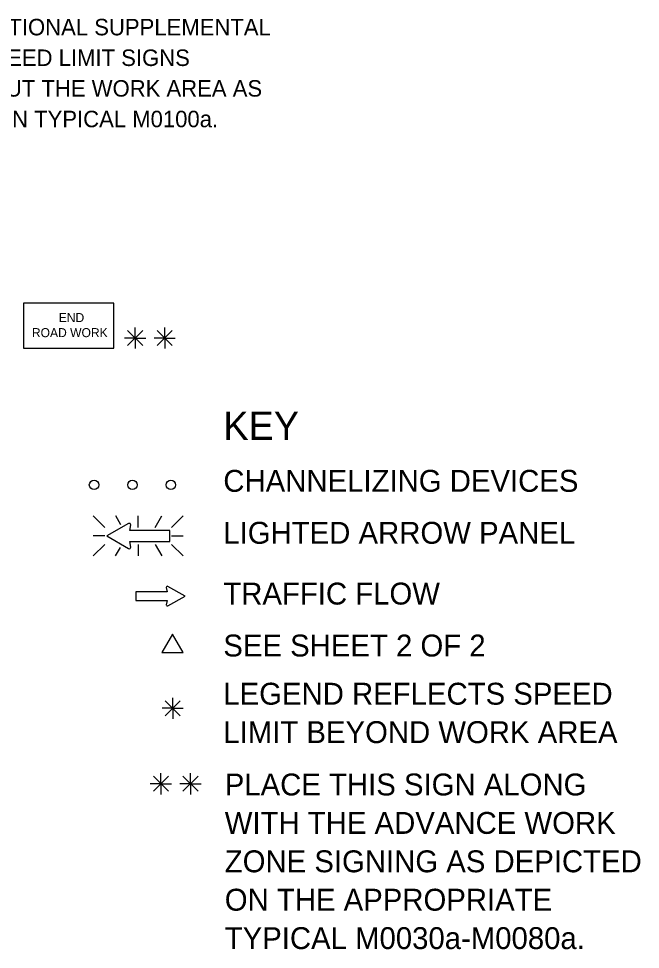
# Model space of a CAD drawing. Extents: x 16284 to 18465, y 5417 to 6974.
# Drawn here: x 17149.1 to 17412.8, y 6528.3 to 6923.3 of the extents above; entities that cross this region are included whole.
import ezdxf

# ---------------------------------------------------------------- set-up
doc = ezdxf.new("R2010")
doc.units = 0
for name, color, linetype in [('MT_SCRATCH_LEVEL_E', 7, 'Continuous'), ('TRAFFIC_SIGNS_PR', 7, 'Continuous'), ('TYPICAL_TEXT_DIMEN_EX', 7, 'Continuous'), ('TYPICAL_TEXT_DIMEN_PR', 7, 'Continuous')]:
    doc.layers.add(name, color=color, linetype=linetype)

msp = doc.modelspace()

# ---------------------------------------------------------------- linework, layer by layer
at = {"layer": 'MT_SCRATCH_LEVEL_E'}
for p, q in [((17211.71, 6681.88), (17212.03, 6680.1)), ((17219.64, 6678.25), (17212.4, 6682.36)), ((17212.03, 6680.1), (17198.77, 6680.1)), ((17198.77, 6680.1), (17198.77, 6676.36)), ((17198.77, 6676.36), (17212.03, 6676.36)), ((17212.03, 6676.36), (17211.71, 6674.58)), ((17212.4, 6674.1), (17219.64, 6678.25))]:
    msp.add_line(p, q, dxfattribs=at)
for centre, start, end in [((17212.17, 6681.95), 60.4248, 189.9638), ((17212.17, 6674.51), 170.0362, 299.7731)]:
    msp.add_arc(centre, 0.463, start, end, dxfattribs=at)
at = {"layer": 'TRAFFIC_SIGNS_PR'}
for p, q in [((17180.7, 6712.26), (17185.64, 6707.33)), ((17192.46, 6708.44), (17190.26, 6712.26)), ((17199.78, 6707.33), (17199.78, 6712.26)), ((17207.02, 6707.33), (17209.87, 6712.26)), ((17213.93, 6707.33), (17218.87, 6712.26)), ((17185.64, 6703.77), (17180.7, 6703.77)), ((17180.7, 6695.28), (17185.64, 6700.21)), ((17199.78, 6700.21), (17199.78, 6695.28)), ((17209.91, 6695.28), (17207.06, 6700.21)), ((17213.93, 6703.77), (17218.87, 6703.77)), ((17213.93, 6700.21), (17218.87, 6695.28)), ((17190.21, 6695.28), (17192.33, 6698.94))]:
    msp.add_line(p, q, dxfattribs=at)
msp.add_lwpolyline([(17151.07, 6783.41), (17189.47, 6783.41), (17189.47, 6802.61), (17151.07, 6802.61)], close=True, dxfattribs=at)
for points in [[(17195.71, 6709.05), (17186.42, 6703.77), (17195.71, 6698.45)], [(17196.59, 6699.08), (17196.19, 6701.35), (17213.2, 6701.35), (17213.2, 6706.15), (17196.19, 6706.15), (17196.59, 6708.43)]]:
    msp.add_lwpolyline(points, dxfattribs=at)
for centre in [(17181.05, 6725.46), (17197.35, 6725.46), (17213.65, 6725.46)]:
    msp.add_circle(centre, 2, dxfattribs=at)
for centre, radius, start, end in [((17196, 6708.52), 0.598, 350.7308, 118.8916), ((17196, 6698.97), 0.597, 241.4833, 9.9593)]:
    msp.add_arc(centre, radius, start, end, dxfattribs=at)
at = {"layer": 'TYPICAL_TEXT_DIMEN_PR'}
for p, q in [((17195.31, 6790.97), (17201.68, 6784.59)), ((17201.68, 6790.97), (17195.31, 6784.59)), ((17198.49, 6787.78), (17198.49, 6792.24)), ((17207.86, 6790.97), (17214.24, 6784.59)), ((17214.24, 6790.97), (17207.86, 6784.59)), ((17211.05, 6787.78), (17211.05, 6792.24)), ((17198.49, 6787.78), (17193.96, 6787.78)), ((17198.49, 6787.78), (17201.68, 6787.78)), ((17198.49, 6787.78), (17202.97, 6787.78)), ((17198.49, 6787.78), (17198.49, 6783.28)), ((17211.05, 6787.78), (17206.52, 6787.78)), ((17211.05, 6787.78), (17214.24, 6787.78)), ((17211.05, 6787.78), (17215.53, 6787.78)), ((17211.05, 6787.78), (17211.05, 6783.28)), ((17211.25, 6633.82), (17217.62, 6627.44)), ((17217.62, 6633.82), (17211.25, 6627.44)), ((17214.43, 6630.63), (17214.43, 6635.09)), ((17214.43, 6630.63), (17209.9, 6630.63)), ((17214.43, 6630.63), (17217.62, 6630.63)), ((17214.43, 6630.63), (17218.91, 6630.63)), ((17214.43, 6630.63), (17214.43, 6626.13)), ((17206.23, 6601.78), (17212.6, 6595.41)), ((17212.6, 6601.78), (17206.23, 6595.41)), ((17209.42, 6598.6), (17209.42, 6603.05)), ((17218.78, 6601.78), (17225.16, 6595.41)), ((17225.16, 6601.78), (17218.78, 6595.41)), ((17221.97, 6598.6), (17221.97, 6603.05)), ((17209.42, 6598.6), (17204.88, 6598.6)), ((17209.42, 6598.6), (17212.6, 6598.6)), ((17209.42, 6598.6), (17213.89, 6598.6)), ((17209.42, 6598.6), (17209.42, 6594.1)), ((17221.97, 6598.6), (17217.44, 6598.6)), ((17221.97, 6598.6), (17225.16, 6598.6)), ((17221.97, 6598.6), (17226.45, 6598.6)), ((17221.97, 6598.6), (17221.97, 6594.1))]:
    msp.add_line(p, q, dxfattribs=at)
msp.add_lwpolyline([(17214.35, 6662.08), (17209.82, 6654.24), (17218.88, 6654.24)], close=True, dxfattribs=at)

# ---------------------------------------------------------------- texts
at = {"layer": 'TRAFFIC_SIGNS_PR'}
for s, height, p in [('PLACE ADDITIONAL SUPPLEMENTAL', 7, (17089.06, 6916.24)), ('SETS OF SPEED LIMIT SIGNS', 7, (17089.06, 6903.24)), ('THROUGHOUT THE WORK AREA AS', 7, (17089.06, 6890.24)), ('DEPICTED ON TYPICAL M0100a.', 7, (17089.06, 6877.24)), ('END', 3.831, (17166.07, 6794.54)), ('ROAD WORK', 3.831, (17154.68, 6788.15))]:
    msp.add_text(s, height=height, dxfattribs=at).set_placement(p)
at = {"layer": 'TYPICAL_TEXT_DIMEN_EX'}
for s, height, p in [('KEY', 12, (17235.89, 6744.56)), ('CHANNELIZING DEVICES', 9.3, (17235.89, 6722.51)), ('LIGHTED ARROW PANEL', 9.3, (17235.89, 6700.46)), ('TRAFFIC FLOW', 9.3, (17235.89, 6674.66)), ('SEE SHEET 2 OF 2', 9.3, (17235.89, 6652.61)), ('LEGEND REFLECTS SPEED', 9.3, (17235.89, 6632.16)), ('LIMIT BEYOND WORK AREA', 9.3, (17235.89, 6615.86)), ('PLACE THIS SIGN ALONG', 9.3, (17236.5, 6593.63)), ('WITH THE ADVANCE WORK', 9.3, (17236.5, 6577.33)), ('ZONE SIGNING AS DEPICTED', 9.3, (17236.5, 6561.03)), ('ON THE APPROPRIATE', 9.3, (17236.5, 6544.73)), ('TYPICAL M0030a-M0080a.', 9.3, (17236.5, 6528.43))]:
    msp.add_text(s, height=height, dxfattribs=at).set_placement(p)

doc.saveas('drawing.dxf')
